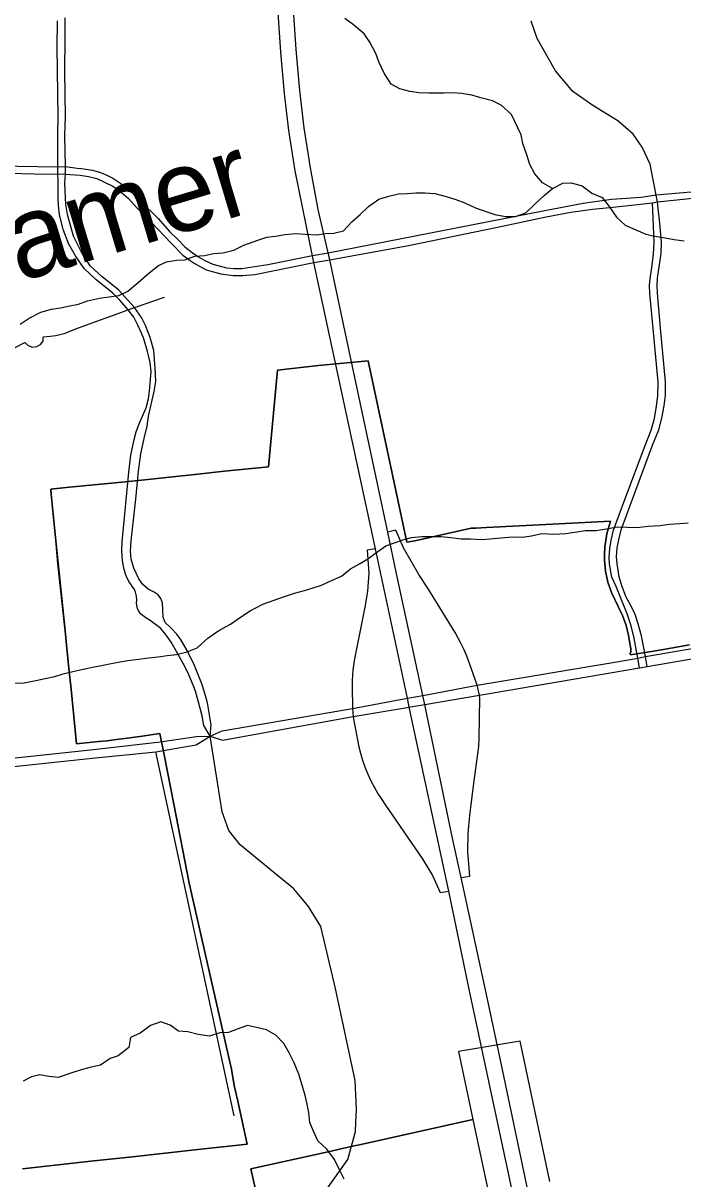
# Model space of a CAD drawing. Extents: x 114843 to 284848, y 317643 to 566895.
# Drawn here: x 165679 to 169692, y 425361 to 432396 of the extents above; entities that cross this region are included whole.
import ezdxf

# ---------------------------------------------------------------- set-up
doc = ezdxf.new("R2010")
doc.units = 0
for name, color, linetype in [('GM_X_City_Street', 7, 'Continuous'), ('GM_X_Corporation', 7, 'Continuous'), ('GM_X_Interchange_Ramps', 7, 'Continuous'), ('GM_X_Interstate_Route', 7, 'Continuous'), ('GM_X_Minor_River', 7, 'Continuous'), ('GM_X_Minor_River_Text', 7, 'Continuous')]:
    doc.layers.add(name, color=color, linetype=linetype)

msp = doc.modelspace()

# ---------------------------------------------------------------- linework, layer by layer
at = {"layer": 'GM_X_City_Street'}
for p, q in [((167009.9, 430902.1), (167062.2, 430910.1)), ((166486.2, 427961), (166543.4, 427970.9)), ((166962.6, 425743.7), (166486.2, 427961))]:
    msp.add_line(p, q, dxfattribs=at)
for points in [[(166480.8, 430320.4), (166473.2, 430402.7), (166452.1, 430481.8), (166423.6, 430555.1), (166398.3, 430603.4), (166357.2, 430664.3), (166259.1, 430771.3), (166158.6, 430851.3), (166086.2, 430918.4), (166034.2, 431001.7), (165985, 431099.7), (165948.8, 431230.2), (165938.1, 431291.1), (165932.8, 431419.5), (165935.6, 431476.4), (165935.7, 431522.4), (165932.9, 431711.1), (165935.7, 431826.4), (165933, 432098.8), (165933.7, 432307.4), (165935, 432428.5)], [(166453.7, 430309.4), (166450.7, 430330.4), (166443.5, 430365.3), (166436.3, 430397), (166413.2, 430474.5), (166399.8, 430508.6), (166376.9, 430558.1), (166352.5, 430605.3), (166317.9, 430650), (166266.3, 430709.7), (166223.5, 430752.8), (166121.7, 430834.6), (166049.2, 430901.6), (165997.5, 430979.4), (165957.4, 431051.2), (165922.8, 431138.5), (165901, 431230.9), (165894.2, 431288.3), (165891.5, 431329.9), (165891.7, 431379.4), (165891, 431437.4), (165890.2, 431477.8), (165890.2, 431521.6), (165890.6, 431726.3), (165891.1, 431825.1), (165886.8, 432249.6), (165888.8, 432409.3)], [(169538, 431308), (169511.9, 431441), (169492.9, 431536.9), (169443.7, 431640.7), (169389.6, 431720), (169295.7, 431801), (169143.4, 431893.2), (169023.2, 431979.8), (168917.3, 432104.5), (168805.1, 432302), (168768.7, 432406.8)], [(167062.2, 430910.1), (167166.6, 430926.2), (167439.3, 430980.2), (167534.6, 430996.5), (168852.4, 431255.1), (169085.7, 431300.4), (169258.1, 431323.5), (169439.3, 431335.7), (169529.5, 431351), (170144.2, 431404.1), (170384.3, 431427.7), (170539.2, 431448.5), (170731, 431500.1), (170942.1, 431595.5), (171042.1, 431659.6), (171216.1, 431767.8), (171375, 431836.7), (171551.6, 431883.8), (171700.8, 431910.9)], [(164091.9, 431526.8), (164445.7, 431516), (164817.1, 431504.3), (165218.6, 431493.3), (165279.7, 431490.1), (165824.1, 431477), (165890.2, 431477.8), (165935.6, 431476.4)], [(164162.6, 431565.5), (164758.7, 431550.2), (165272.6, 431534.5), (165521.3, 431527.6), (165890.2, 431521.6), (165935.7, 431522.4), (166008.3, 431513.3)], [(166008.3, 431513.3), (166034.3, 431510), (166101.6, 431500.3), (166150.1, 431485.7), (166188.4, 431470), (166224.3, 431450.9), (166285.6, 431411.2), (166332.8, 431371.9), (166395.2, 431308.9), (166499.2, 431207.4), (166570.1, 431126.8), (166619.2, 431077.8), (166663.4, 431034.8), (166706.3, 430999.3), (166741, 430975.8), (166784.4, 430949.8), (166833.3, 430929.2), (166871.2, 430918), (166916.6, 430906.8), (166962.6, 430901.7), (167009.9, 430902.1)], [(165935.6, 431476.4), (166025.1, 431470.5), (166076.9, 431462.3), (166127.6, 431449.7), (166224.8, 431403.1), (166263.8, 431376.4), (166319, 431328.4), (166373.3, 431269.6), (166460, 431183), (166579.4, 431055.7), (166649.9, 430984.1), (166714.8, 430937.2), (166792.7, 430894.7), (166882.2, 430870.5), (166956.3, 430860), (167014.6, 430859.5)], [(167014.6, 430859.5), (167087.8, 430865.8), (167447.7, 430939.3), (167544.3, 430955.1), (168023.3, 431041.8), (168564.2, 431154.3), (168861.4, 431217.1), (169010.8, 431245), (169141.9, 431262.9), (169246.2, 431273.5), (169360.4, 431285.6), (169507, 431302.2), (169538, 431308), (169791.7, 431333.9)], [(169427.7, 428470.9), (169417.8, 428530.9), (169394.4, 428663), (169375.8, 428733.9), (169353.8, 428800.3), (169314.3, 428895.4), (169285.4, 428966.7), (169259.4, 429023.7), (169246.3, 429102.9), (169242.8, 429145.6), (169247.7, 429198.8), (169256.7, 429248.9), (169270.9, 429308.4), (169339.4, 429496.6), (169462.1, 429823.8), (169500, 429917.9), (169519.3, 429988.9), (169532.3, 430064.1), (169540.2, 430127.7), (169541.7, 430210.1), (169511.2, 430536.2), (169491.9, 430749.8), (169489.5, 430797.7), (169493.4, 430841.5), (169502.3, 430907.3), (169514.2, 430991.8), (169516.8, 431061.7), (169507, 431302.2)], [(169475.3, 428479.6), (169465.3, 428539.6), (169439.6, 428665.5), (169419.3, 428738.3), (169399, 428802.8), (169366.2, 428868.3), (169347.2, 428902.5), (169320.6, 428970.1), (169304.6, 429026.3), (169291.5, 429105.4), (169288.1, 429148.1), (169292.9, 429201.3), (169301.9, 429251.4), (169316.1, 429311), (169384.6, 429499.1), (169507.3, 429826.3), (169545.2, 429920.4), (169564.5, 429991.4), (169577.5, 430066.6), (169585.4, 430130.3), (169586.9, 430212.6), (169556.4, 430538.7), (169537.2, 430752.3), (169534.7, 430800.2), (169538.6, 430844.1), (169547.5, 430909.8), (169559.4, 430994.3), (169562, 431064.2), (169549.6, 431198.6), (169540.7, 431267.3), (169538, 431308)], [(164251.4, 430228.2), (164286.8, 430237.3), (164800.1, 430313.9), (165092.2, 430337), (165425.3, 430376.7), (165513.9, 430387.5), (165573.6, 430399.6), (165629.4, 430421), (165688.3, 430452.5), (165710.2, 430432.4), (165735.1, 430424.1), (165761.5, 430427.4), (165784.5, 430439.7), (165801, 430459.5), (165800.8, 430486.7), (165843.5, 430490.9), (165878.4, 430493.5), (165928.1, 430507), (166015.7, 430540.3), (166317.9, 430650), (166357.2, 430664.3), (166539, 430727.5)], [(166368.7, 429540.8), (166381.2, 429669.3), (166393.8, 429773.4), (166414.2, 429868.1), (166432.4, 429942.5), (166441.4, 430002.8), (166476.5, 430153), (166486.3, 430213.3), (166482.8, 430298.5), (166480.8, 430320.4)], [(166382.8, 428815.7), (166373.8, 428830.4), (166369.3, 428864.5), (166369.9, 428883.1), (166369, 428908), (166362.2, 428931.2), (166356.6, 428947.5), (166337.8, 428975.3), (166321.7, 428997.7), (166305.6, 429031.8), (166292.8, 429070.7), (166286, 429109.7), (166281.4, 429149.2), (166280, 429191.1), (166280.8, 429237.7), (166305.4, 429491.4), (166322.1, 429662.7), (166334.7, 429766.8), (166355.1, 429861.6), (166367.2, 429907.3), (166380.5, 429947.4), (166395.8, 429985.6), (166426.3, 430053), (166442.2, 430109), (166446.7, 430156.5), (166454.4, 430225.5), (166458.2, 430278.1), (166453.7, 430309.4)], [(166523.1, 428878), (166517.4, 428893.9), (166499.2, 428914.9), (166474.9, 428931.9), (166439.6, 428950.4), (166407.3, 428979.1), (166382.8, 429014.1), (166351.9, 429077.2), (166335.8, 429133.4), (166331.6, 429181.1), (166335, 429243.6), (166364.5, 429497.9), (166368.7, 429540.8)], [(166815.8, 428054.8), (166890.4, 428087.4), (167681.8, 428223.8), (168016.8, 428286), (168110.9, 428303.1), (168441.5, 428365.7), (169289.4, 428507.2), (169417.8, 428530.9), (169465.3, 428539.6), (170100.6, 428650.2), (170924.2, 428798.6), (171573.8, 428918), (171665.2, 428907.5)], [(166815.8, 428054.8), (166822.6, 428124.2), (166800.3, 428258.7), (166780.2, 428330.4), (166765.1, 428374.9), (166722, 428484.9), (166676.8, 428576), (166640.4, 428639.1), (166613.6, 428676.4), (166575.7, 428716.8), (166543.5, 428747.9), (166530.7, 428779.8), (166528.1, 428823.6), (166527, 428867.4), (166523.1, 428878)], [(166815.8, 428054.8), (166778.8, 428119.6), (166767.5, 428178.6), (166745.2, 428262.3), (166726.4, 428329.7), (166716.2, 428356.4), (166683.7, 428438.1), (166653, 428498.1), (166620.4, 428556.1), (166579.5, 428627.6), (166561.4, 428654.7), (166542.6, 428678.6), (166516.6, 428710.3), (166484.7, 428736), (166452.3, 428759.5), (166424.3, 428775.6), (166391.9, 428801), (166382.8, 428815.7)], [(168455.7, 428305.4), (169427.7, 428470.9), (169475.3, 428479.6), (170110.6, 428590.1), (170167.5, 428601.8)], [(168047.4, 428235.5), (168122.6, 428248.3), (168455.7, 428305.4)], [(167686.5, 428174.8), (168027.4, 428232.1), (168047.4, 428235.5)], [(166815.8, 428054.8), (166891.1, 428030.2), (167686.5, 428174.8)], [(164045.2, 427759.6), (164492.5, 427804.8), (165248.3, 427882.2), (166107.7, 427974.2), (166477.1, 428016.8), (166498.4, 428019.8)], [(166498.4, 428019.8), (166732.7, 428053.3), (166815.8, 428054.8)], [(166543.4, 427970.9), (166731.9, 428003.2), (166815.8, 428054.8)], [(167344.9, 427102.2), (167325.2, 427126.1), (167202.9, 427226.6), (166999, 427394), (166930.7, 427481.4), (166889.4, 427596), (166815.8, 428054.8)], [(164477.3, 427751.5), (164482.6, 427752.1), (165238.4, 427829.4), (166097.8, 427921.5), (166486.2, 427961)], [(167703.2, 425706.1), (167706.6, 425784.1), (167698.6, 425959.7), (167579.6, 426519.7), (167489.1, 426897.5), (167413.9, 427018.6), (167344.9, 427102.2)], [(167520.9, 425289.4), (167654.7, 425479.6), (167700.8, 425648.9), (167703.2, 425706.1)]]:
    msp.add_lwpolyline(points, dxfattribs=at)
at = {"layer": 'GM_X_Corporation'}
for points in [[(169732, 428612), (169562, 428581.5), (169514, 428572.9), (169372.8, 428550.7), (169371.1, 428559.4), (169374.6, 428567.9), (169375.9, 428577.1), (169375, 428586.3), (169365.2, 428643.6), (169358.9, 428680.1), (169345.2, 428735.7), (169325.7, 428789.7), (169297.8, 428844.5), (169258.1, 428929.2), (169236.3, 428993.2), (169221.8, 429059.3), (169214.9, 429126.7), (169215.1, 429158.7), (169216.6, 429207.2), (169228.9, 429286.8), (169251.8, 429364.1), (168898.3, 429346.2), (168497, 429325.9), (168433.5, 429322.5), (168403.3, 429321.6), (168062.1, 429244.4), (168012.5, 429235.4), (167900.4, 429760.8), (167776.7, 430340), (167476.1, 430311.3), (167227, 430283.3), (167172.3, 429695.9), (166903.6, 429667.6), (166741.7, 429650.6), (166380, 429612.7), (166299.3, 429603.9), (165939.7, 429568.8), (165846.5, 429558.7), (165849.4, 429528.8), (165878.9, 429224), (165934.1, 428696.1), (165942.9, 428612), (165959.3, 428448.1), (165968, 428362.8), (166004, 428009.9), (166137, 428022.2), (166189.9, 428028), (166260.4, 428036.4), (166297, 428041), (166403.7, 428056.1), (166510.4, 428071.7), (166539.8, 427922), (166594.8, 427641.8), (166689.4, 427160.1), (166924.2, 426125.7), (166945.9, 426028.1), (166962.7, 425929.4), (166984.1, 425833), (167041.8, 425573.2), (166986.9, 425567.1), (166759.2, 425541.9), (166542.5, 425517.9), (166325.8, 425493.8), (166109.1, 425469.8), (165892.4, 425445.8), (165675.8, 425421.8)], [(165675.8, 425421.8), (165892.4, 425445.8), (166109.1, 425469.8), (166325.8, 425493.8), (166542.5, 425517.9), (166759.2, 425541.9), (166986.9, 425567.1), (167041.8, 425573.2), (166984.1, 425833), (166962.7, 425929.4), (166945.9, 426028.1), (166924.2, 426125.7), (166689.4, 427160.1), (166594.8, 427641.8), (166539.8, 427922), (166510.4, 428071.7), (166403.7, 428056.1), (166297, 428041), (166260.4, 428036.4), (166189.9, 428028), (166137, 428022.2), (166004, 428009.9), (165968, 428362.8), (165959.3, 428448.1), (165942.9, 428612), (165934.1, 428696.1), (165890.5, 429103.7), (165878.9, 429224), (165849.4, 429528.8), (165846.5, 429558.7), (165939.7, 429568.8), (166299.3, 429603.9), (166380, 429612.7), (166741.7, 429650.6), (166903.6, 429667.6), (167172.3, 429695.9), (167227, 430283.3), (167476.1, 430311.3), (167776.7, 430340), (168012.5, 429235.4), (168062.1, 429244.4), (168403.3, 429321.6), (168433.5, 429322.5), (168497, 429325.9), (168898.3, 429346.2), (169251.8, 429364.1), (169228.9, 429286.8), (169216.6, 429207.2), (169215.1, 429158.7), (169214.9, 429126.7), (169221.8, 429059.3), (169236.3, 428993.2), (169258.1, 428929.2), (169297.8, 428844.5), (169325.7, 428789.7), (169345.2, 428735.7), (169358.9, 428680.1), (169365.2, 428643.6), (169375, 428586.3), (169375.9, 428577.1), (169374.6, 428567.9), (169371.1, 428559.4), (169372.8, 428550.7), (169514, 428572.9), (169562, 428581.5), (169732, 428612)], [(168883.7, 425345.8), (168830.6, 425594.7), (168806.1, 425709.4), (168701.6, 426198.9), (168326.4, 426136.3), (168414.8, 425722.1), (167725.1, 425569), (167692.6, 425561.8), (167602.8, 425541.8), (167552.3, 425530.6), (167064.7, 425422.3), (167144.4, 425062.8)], [(167144.4, 425062.8), (167064.7, 425422.3), (167552.3, 425530.6), (167602.8, 425541.8), (167692.6, 425561.8), (167725.1, 425569), (168414.8, 425722.1), (168465.5, 425484.5), (168528.2, 425191)]]:
    msp.add_lwpolyline(points, dxfattribs=at)
at = {"layer": 'GM_X_Interchange_Ramps'}
msp.add_line((167681.8, 428223.8), (167686.5, 428174.8), dxfattribs=at)
for points in [[(168455.7, 428305.4), (168441.5, 428365.7), (168392.8, 428503.7), (168377.8, 428543.2), (168361.8, 428580.9), (168342.1, 428622.5), (168307.8, 428685.7), (168139.9, 428957.3), (168085.8, 429040), (167992.9, 429202.4), (167945.8, 429308.6), (167896.9, 429296.6)], [(167822.7, 429195.3), (167770.6, 429188), (167782, 429046.8), (167773.6, 428939), (167759.1, 428850.9), (167741, 428760.4)], [(167741, 428760.4), (167694, 428526.3), (167684.8, 428458.4), (167680.7, 428395.1), (167680.2, 428355.2), (167681.8, 428223.8)], [(168419.3, 427753.6), (168436.8, 427890.1), (168445.7, 427948.1), (168450, 427993.4), (168452.1, 428041.8), (168456.6, 428286.4), (168455.7, 428305.4)], [(167686.5, 428174.8), (167690.9, 428149.8), (167712.2, 428033.2), (167720.9, 427990.9), (167732.9, 427944), (167745.4, 427903.4), (167759.6, 427863.4), (167775.2, 427825), (167794, 427784), (167815.5, 427742.6), (167838.9, 427702.3), (167859.8, 427669.8), (167879.3, 427641.4)], [(168344.3, 427195.3), (168396.4, 427204), (168383.7, 427351), (168386.4, 427462.2), (168396, 427573.5), (168419.3, 427753.6)], [(167879.3, 427641.4), (168110.8, 427305), (168169.4, 427208.2), (168216.4, 427103.1), (168268.7, 427111.2)]]:
    msp.add_lwpolyline(points, dxfattribs=at)
at = {"layer": 'GM_X_Interstate_Route'}
for points in [[(167822.7, 429195.3), (167447.7, 430939.3), (167333.4, 431497), (167295.7, 431741.1), (167268.6, 431967.9), (167246, 432217.9), (167230.3, 432460.9), (167223.6, 432757.4), (167226.1, 433046.9), (167241.5, 433347.6), (167281.5, 433740.5), (167333.4, 434065.7), (167390.3, 434395.7), (167460, 434692.6), (167528.8, 434943.3), (167611.5, 435203.3), (167764, 435610.9), (167857, 435840.9), (167910.6, 435957.4)], [(167696.7, 430238.3), (167544.3, 430955.1), (167472.6, 431261.7), (167426.8, 431515), (167389.1, 431759.1), (167362, 431985.9), (167339.4, 432235.8), (167323.7, 432478.9), (167317, 432775.4), (167319.5, 433064.9), (167336.9, 433383.5), (167379.2, 433777.6), (167426.8, 434083.7), (167487.1, 434398), (167555.7, 434682.2), (167638.1, 434976.9), (167723.2, 435227.7), (167812.8, 435475.4), (167849.2, 435576.1), (167917.7, 435742.2), (167956.5, 435828)], [(168133, 428198), (168122.6, 428248.3), (168110.9, 428303.1), (167948.3, 429053.1), (167896.9, 429296.6), (167696.7, 430238.3)], [(168268.7, 427111.2), (168027.4, 428232.1), (168016.8, 428286), (167822.7, 429195.3)], [(168587.9, 426054.1), (168497.2, 426483.7), (168344.3, 427195.3), (168293.6, 427423.9), (168133, 428198)], [(171474.3, 412035.7), (171312.4, 412767.5), (171241.7, 413148.7), (171057.8, 414018.5), (170637.6, 415985.9), (169978.9, 419070.3), (169481.1, 421425.2), (169325.4, 422146.7), (168984.9, 423732.7), (168808.8, 424560), (168394.5, 426505.7), (168268.7, 427111.2)], [(169616.3, 421231.6), (169573.6, 421433.9), (169417.8, 422155.4), (169077.4, 423761.6), (168901.3, 424568.7), (168587.9, 426054.1)]]:
    msp.add_lwpolyline(points, dxfattribs=at)
at = {"layer": 'GM_X_Minor_River'}
for points in [[(168898.8, 431389.4), (168839, 431423.9), (168791.3, 431478.3), (168761.6, 431534.6), (168742, 431594.9), (168718.4, 431663.2), (168708.7, 431715.4), (168649.4, 431840.1), (168585.7, 431896.6), (168533.8, 431923), (168464, 431941.5), (168408, 431957.8), (168346.1, 431968.2), (168290.1, 431970.6), (168240.1, 431968.9), (168146.1, 431969.4), (168086.1, 431971.8), (168032.1, 431980.1), (167970.2, 431996.5), (167918.4, 432024.9), (167874.7, 432091.4), (167843.1, 432159.7), (167823.4, 432210), (167787.8, 432280.4), (167754.1, 432330.7), (167688.4, 432385.2), (167636.6, 432423.6)], [(165661.6, 430562.5), (165715.8, 430600.3), (165786, 430635.9), (165852.2, 430653.6), (165906.2, 430663.3), (165962.3, 430675), (166016.4, 430684.7), (166070.5, 430704.4), (166142.6, 430722.1), (166202.6, 430729.7), (166260.7, 430737.4), (166314.9, 430765.1), (166379.2, 430816.9), (166445.5, 430876.7), (166501.8, 430920.4), (166551.9, 430942.2), (166612, 430951.9), (166662, 430955.6), (166724.2, 430977.3), (166784.2, 430980.9), (166836.3, 430992.7), (166894.3, 430998.3), (166960.4, 431014), (167020.6, 431043.7), (167106.8, 431075.3), (167160.9, 431093), (167214.9, 431098.7), (167273, 431108.4), (167337, 431116), (167397, 431111.6), (167463, 431107.2), (167517.1, 431114.9), (167569.1, 431116.6), (167627.2, 431132.3), (167677.5, 431186.2), (167729.8, 431230), (167780, 431279.8), (167842.3, 431323.5), (167902.4, 431343.2), (167962.5, 431356.9), (168014.5, 431358.6), (168066.6, 431362.3), (168122.6, 431362), (168182.6, 431357.6), (168252.5, 431341.1), (168310.4, 431322.8), (168366.3, 431302.4), (168434.1, 431269.9), (168547.9, 431231.1), (168613.8, 431218.7), (168673.8, 431218.3), (168736, 431240), (168792.3, 431293.8), (168848.6, 431345.6), (168898.8, 431389.4), (168961, 431421.1), (169013, 431422.8), (169078.9, 431404.4), (169138.7, 431359.9), (169200.6, 431333.5), (169244.3, 431279.1), (169287.9, 431214.7), (169341.6, 431166.2), (169405.5, 431137.7), (169467.3, 431111.3), (169521.3, 431099), (169585.2, 431088.5), (169639.2, 431078.2), (169699.1, 431069.8)], [(165620.9, 428378.8), (165684.9, 428380.4), (165757, 428394.1), (165813.1, 428405.8), (165871.2, 428419.4), (165923.3, 428435.2), (165981.4, 428448.9), (166035.5, 428460.6), (166101.6, 428476.2), (166155.6, 428485.9), (166213.7, 428497.6), (166313.8, 428517.1), (166381.9, 428524.7), (166441.9, 428532.4), (166500, 428538), (166554, 428545.7), (166612.1, 428553.4), (166676.2, 428569.1), (166738.3, 428592.8), (166802.7, 428652.5), (166869, 428698.3), (166939.2, 428738), (167001.5, 428779.7), (167059.7, 428817.5), (167136, 428859.1), (167200.1, 428880.8), (167256.2, 428902.5), (167330.4, 428926.2), (167390.5, 428941.8), (167442.6, 428957.6), (167494.7, 428975.3), (167554.8, 429003), (167615, 429028.7), (167669.3, 429074.5), (167725.5, 429104.3), (167775.6, 429134.1), (167835.9, 429179.8), (167886.1, 429213.6), (167938.2, 429231.4), (167988.4, 429251.1), (168040.4, 429264.9), (168104.5, 429270.5), (168162.5, 429270.1), (168222.5, 429271.8), (168280.5, 429265.4), (168342.4, 429257), (168400.5, 429256.7), (168468.4, 429252.3), (168518.5, 429256), (168586.5, 429263.6), (168652.6, 429269.2), (168714.6, 429266.9), (168770.6, 429274.5), (168834.7, 429288.2), (168906.7, 429285.8), (168980.7, 429289.3), (169046.8, 429299), (169096.8, 429306.7), (169164.9, 429308.3), (169226.9, 429317.9), (169293, 429329.6), (169351, 429327.2), (169411, 429324.9), (169481.1, 429334.5), (169553.1, 429338), (169611.1, 429345.7), (169673.2, 429349.4), (169723.2, 429353.1)], [(167631.4, 425360.1), (167603.7, 425416.5), (167572, 425478.9), (167526.4, 425541.3), (167470.7, 425591.8), (167445.1, 425652.1), (167423.4, 425704.4), (167417.7, 425764.6), (167406, 425814.8), (167394.4, 425869.1), (167376.7, 425931.4), (167355.1, 425997.7), (167327.5, 426068.1), (167297.9, 426128.4), (167264.2, 426184.8), (167216.5, 426235.2), (167158.7, 426267.7), (167098.8, 426282.1), (167042.8, 426294.4), (166980.7, 426272.7), (166928.6, 426251), (166874.6, 426249.3), (166812.4, 426229.6), (166744.5, 426240), (166680.6, 426256.5), (166624.6, 426260.8), (166572.8, 426297.2), (166516.9, 426317.6), (166452.8, 426293.9), (166390.5, 426248.2), (166332.3, 426222.4), (166321.9, 426160.3), (166257.6, 426110.6), (166207.5, 426092.8), (166149.3, 426053), (166093.2, 426041.3), (166031.1, 426023.7), (165975, 426005.9), (165892.8, 425978.3), (165834.8, 425984.7), (165780.9, 425995.1), (165728.8, 425981.3), (165678.6, 425955.6)]]:
    msp.add_lwpolyline(points, dxfattribs=at)

# ---------------------------------------------------------------- texts
at = {"layer": 'GM_X_Minor_River_Text'}
msp.add_text('Cramer', height=500.03, rotation=16.7572, dxfattribs=at).set_placement((164978, 430615.4))

doc.saveas('drawing.dxf')
